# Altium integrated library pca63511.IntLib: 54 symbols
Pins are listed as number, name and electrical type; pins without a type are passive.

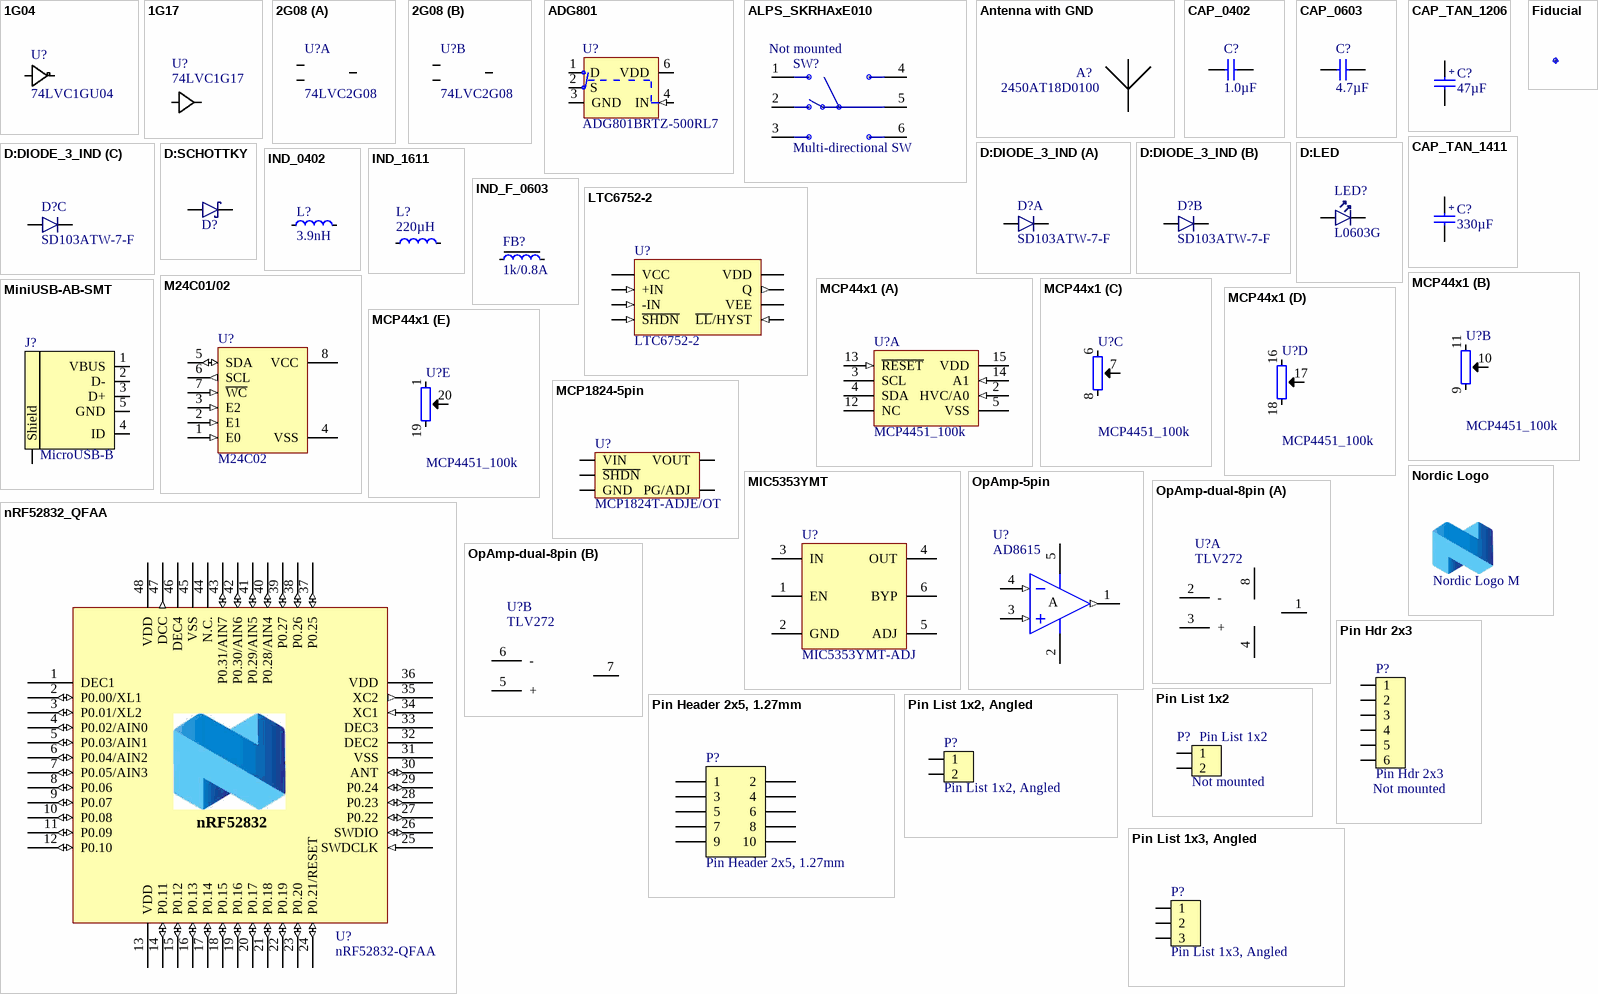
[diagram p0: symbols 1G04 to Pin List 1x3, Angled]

## 1G04
designator U?, comment 74LVC1GU04
Unbuffered Inverter; Manufacturer: NXP Semiconductors; 2nd source part number: 163-1691; Artikkelnr Noca: 15049405; Artikkelnr Simpro: N.A.
footprint SOT-353
pins: 1 N.C. hidden, 2 A, 3 GND hidden to GND, 4 Y, 5 VDD hidden to VDD

## 1G17
designator U?, comment 74LVC1G17
Single schmitt-trigger buffer with standard push-pull output; Part Number: 74LVC1G17SE; Manufacturer: Diodes; 2nd source part number: 189-3834; Artikkelnr Noca: 15049066; Artikkelnr Simpro: N.A.
footprint SOT-353
pins: 1 N.C. hidden, 2 A, 3 GND hidden to GND, 4 Y, 5 VDD hidden to VDD

## 2G08
designator U?, comment 74LVC2G08
IC DUAL 2IN POS-AND GATE SOT-1089; Part Number: 74LVC2G08GF; Manufacturer: NXP; Note: DUAL 2-INPUT POSITIVE-AND GATE; Artikkelnr Noca: 15049067; Artikkelnr Simpro: N.A.
footprint PSON35P100X50-8N
part A pins: 1 1A, 2 1B, 4 GND (power) hidden to GND "Ground", 7 1Y, 8 VDD (power) hidden to VDD
part B pins: 3 2Y, 5 2A, 6 2B

## ADG801
designator U?, comment ADG801BRTZ-500RL7
SWITCH SPST SOT23-6; Manufacturer: Analog Devices; 2nd source part number: 237-6778; Note: -40°C ~ 125°C; Artikkelnr Noca: 15079991; Artikkelnr Simpro: N.A.
footprint SOT95P280X145-6N
pins: 1 D, 2 S, 3 GND (power), 4 IN (in), 6 VDD (power)

## ALPS_SKRHAxE010
designator SW?, comment Multi-directional SW  Assembly: Not mounted
ALPS - SKRHAAE010, Multi-directional Switches 4-directn cntr push w/o boss 200K cycles, SMD, 7.5x7.5x5mm; Part Number: ALPS_SKRHAAE010; Artikkelnr Noca: 50019040; Artikkelnr Simpro: N.A.
footprint ALPS_SKRHAAE010
pins: 1 (power), 2 (power), 3 (power), 4 (power), 5 (power), 6 (power)

## Antenna with GND
designator A?, comment 2450AT18D0100
2.45 GHz chip antenna; Part Number: Johanson 2450AT18D0100_STD; Manufacturer: Johanson Technology; 2nd source part number: 609-2450AT18D0100E; Artikkelnr Noca: 53059035; Artikkelnr Simpro: N.A.
footprint 2450AT18D0100_STD
pins: 1, 2 GND (power) hidden to GND

## CAP_0402
designator C?, comment 1.0µF
Capacitor, X5R, ±5%; Part Number: C0402-1µ0; Note: 6.3V; Artikkelnr Noca: 20039235; Artikkelnr Simpro: N.A.
footprint CAPC1005X04L
pins: 1, 2

## CAP_0603
designator C?, comment 4.7µF
Capacitor, X5R, ±10%; Part Number: C0603-4µ7; Note: 6.3V; Artikkelnr Noca: 20069060; Artikkelnr Simpro: N.A.
footprint CAPC1608X06L
pins: 1, 2

## CAP_TAN_1206
designator C?, comment 47µF
Capacitor, Tantalum, ±10%; Part Number: C1206-47µ_Tantal; Note: 10V; Artikkelnr Noca: 20049200; Artikkelnr Simpro: N.A.
footprint CAPMP3216X18N
pins: 1, 2

## CAP_TAN_1411
designator C?, comment 330µF
Capacitor, Tantalum, ±20%, 3528; Part Number: C3528-330µF; Manufacturer: Kemet; Manufacturer Part Number: T490B337M006ATE800; Note: 6.3V; Artikkelnr Noca: 20049201; Artikkelnr Simpro: N.A.
footprint CAPMP3528X21N
pins: 1, 2

## D:DIODE_3_IND
designator D?, comment SD103ATW-7-F
Surface Mount Schottky Barrier Diode Array; Manufacturer: Diodes Incorporated; 2nd source part number: 177-3507; Artikkelnr Noca: 10029109; Artikkelnr Simpro: N.A.
footprint SOT-363
part A pins: 1 C1, 6 A1
part B pins: 2 C2, 5 A2
part C pins: 3 C3, 4 A3

## D:LED
designator LED?, comment L0603G
LED 0603, EL19-21SYGC; Manufacturer: Everlight; Manufacturer Part Number: 19-21SYGC/S530-E1/TR8; Note: 16 mcd @ 20 mA; Artikkelnr Noca: 13019044; Artikkelnr Simpro: N.A.
footprint LED_0603_G
pins: 1 C, 2 A

## D:SCHOTTKY
designator D?, comment 1PS79SB30.115  (value not drawn)
Diode Schottky Vf=0.38, Vr=40V, If=200mA, Ir=500nA; Manufacturer: NXP; Artikkelnr Noca: 10029120; Artikkelnr Simpro: N.A.
footprint SOD-523
pins: 1 A, 3 C

## Fiducial
designator Fid?, comment Fiducial mark  (value not drawn)
Part Number: Fid-Mark; Artikkelnr Noca: N.A.
footprint Fiducial

## IND_0402
designator L?, comment 3.9nH
Inductor, 170mA, ±0.1nH; Part Number: L0402-3n9; Manufacturer: Murata; Manufacturer Part Number: LQP15MN3N9B02D; Note: High frequency chip inductor ±5%; Artikkelnr Noca: 33029151; Artikkelnr Simpro: N.A.
footprint INDC1005X04L
pins: 1, 2

## IND_1611
designator L?, comment 220µH
FIXED IND 470UH 240MA 2.6 OHM; Part Number: L4848-220µH; Manufacturer: Bourns; Manufacturer Part Number: SRR4028-221Y; Note: -40°C ~ 125°C; Artikkelnr Noca: 33020083; Artikkelnr Simpro: N.A.
footprint WE-TPC_4848
pins: 1, 2

## IND_F_0603
designator FB?, comment 1k/0.8A
Ferrite Bead, 1 kOhm @ 100MHz, 800mA, 300 mOhm Max; Part Number: FB0603-1k@100MHz-800mA; Manufacturer: TDK; Manufacturer Part Number: MPZ1608S102ATA00; Note: Chip EMIFIL Inductor Type Chip Ferrite Bead; Artikkelnr Noca: 37029017; Artikkelnr Simpro: N.A.
footprint INDC1608X06L
pins: 1, 2

## LTC6752-2
designator U?
IC 2.9ns COMPARATOR, Rail-to-Rail input CMOS output, MSOP-8; Manufacturer: Linear Technology; Artikkelnr Noca: 17029058; Artikkelnr Simpro: N.A.
footprint MSOP65P490X110-8N
pins: 1 VCC (power), 2 +IN (in), 3 -IN (in), 4 ~{SHDN} (in), 5 ~{LL}/HYST (in), 6 VEE (power), 7 Q (out), 8 VDD (power)

## M24C01/02
designator U?, comment M24C02
2-Kbit serial I²C bus EEPROM; Part Number: M24C02-FDW6TP; Manufacturer: STMicroelectronics; Artikkelnr Noca: 15020011; Artikkelnr Simpro: N.A.
footprint TSOP65P640X120-8N
pins: 1 E0 (in), 2 E1 (in), 3 E2 (in), 4 VSS (power), 5 SDA (io), 6 SCL (out), 7 ~{WC} (in), 8 VCC (power)

## MCP44x1
designator U?, comment MCP4451_100k
Quad Digital Potentiometer, 100k, 257 taps, I2C interface, Volatile Memory, 1.8-5.5V; Manufacturer: Microchip Technology; Manufacturer Part Number: MCP4451-104E/ML; 2nd source part number: 579-MCP4451-104E/ML; Artikkelnr Noca: 15070064; Artikkelnr Simpro: N.A.
footprint QFN50P400X400X80_HS-21N
part A pins: 2 HVC/A0 (in), 3 SCL, 4 SDA, 5 VSS (power), 12 NC, 13 ~{RESET} (in), 14 A1 (in), 15 VDD (power) "VDD 1.65V - 5.5V", 21 VSS (power) hidden to GND
part B pins: 9 P0A, 10 P0W (power), 11 P0B
part C pins: 6 P1B, 7 P1W (power), 8 P1A
part D pins: 16 P2B, 17 P2W (power), 18 P2A
part E pins: 1 P3B, 19 P3A, 20 P3W (power)

## MCP1824-5pin
designator U?, comment MCP1824T-ADJE/OT
300 mA, Low Voltage, Low Quiescent Current LDO Regulator; Manufacturer: Microchip; Artikkelnr Noca: 17030009; Artikkelnr Simpro: N.A.
footprint SOT-23-5
pins: 1 VIN, 2 GND, 3 ~{SHDN}, 4 PG/ADJ, 5 VOUT

## MIC5353YMT
designator U?, comment MIC5353YMT-ADJ
500mA LDO adjustable; Manufacturer: Microchip Technology; Artikkelnr Noca: 17030072; Artikkelnr Simpro: N.A.
footprint QFN50P160X160X60_6N
pins: 1 EN, 2 GND (power), 3 IN (power), 4 OUT (power), 5 ADJ (power), 6 BYP (power), 7 GND hidden to GND

## MiniUSB-AB-SMT
designator J?, comment MicroUSB-B
MicroUSB-B-SMT; Part Number: USB-Micro-B-RA-SMD-PiP; Manufacturer: Allen Creations Corp.; Manufacturer Part Number: AJU55-BS2111-L; 2nd source part number: 609-4616-1-ND; Artikkelnr Noca: 55029020; Artikkelnr Simpro: N.A.
footprint USB-Micro-B-RA-SMD-PiP
pins: 1 VBUS (power), 2 D-, 3 D+, 4 ID, 5 GND (power), 6 Shield (power)

## Nordic Logo
designator LOGO?, comment Nordic Logo M  (no BOM)
Nordic Logo, medium size; Artikkelnr Noca: N.A.
footprint NORDIC_LOGO_M

## nRF52832_QFAA
designator U?, comment nRF52832-QFAA
Multi-protocol Bluetooth Low Energy and 2.4GHz proprietary system-on-chip; Manufacturer: Nordic Semiconductor; Artikkelnr Noca: 15079306; Artikkelnr Simpro: N.A.
footprint QFN40P600X600X90-48N
pins: 1 DEC1 (power), 2 P0.00/XL1 (io), 3 P0.01/XL2 (io), 4 P0.02/AIN0 (io), 5 P0.03/AIN1 (io), 6 P0.04/AIN2 (io), 7 P0.05/AIN3 (io), 8 P0.06 (io), 9 P0.07 (io), 10 P0.08 (io), 11 P0.09 (io), 12 P0.10 (io), 13 VDD (power), 14 P0.11 (io), 15 P0.12 (io), 16 P0.13 (io), 17 P0.14 (io), 18 P0.15 (io), 19 P0.16 (io), 20 P0.17 (io), 21 P0.18 (io), 22 P0.19 (io), 23 P0.20 (io), 24 P0.21/RESET (io), 25 SWDCLK (in), 26 SWDIO (io), 27 P0.22 (io), 28 P0.23 (io), 29 P0.24 (io), 30 ANT (io), 31 VSS (power), 32 DEC2 (power), 33 DEC3 (power), 34 XC1 (in), 35 XC2 (out), 36 VDD (power), 37 P0.25 (io), 38 P0.26 (io), 39 P0.27 (io), 40 P0.28/AIN4 (io), 41 P0.29/AIN5 (io), 42 P0.30/AIN6 (io), 43 P0.31/AIN7 (io), 44 N.C. (power), 45 VSS (power), 46 DEC4 (power), 47 DCC (out), 48 VDD (power), 49 GND (power) hidden to GND

## OpAmp-5pin
designator U?, comment AD8615
IC OPAMP GP 24MHZ RRO TSOT23-5; Part Number: AD8615AUJZ-REEL7; Manufacturer: Analog Devices; Artikkelnr Noca: 17010015; Artikkelnr Simpro: N.A.
footprint SOT95P280X145-5N
pins: 1 OUT (out), 2 VSS (power), 3 IN+ (in), 4 IN- (in), 5 VDD (power)

## OpAmp-dual-8pin
designator U?, comment TLV272
Dual rail to rail CMOS Amplifier; Part Number: TLV272CM8-13; Manufacturer: Diodes Incorporated; Artikkelnr Noca: 17010014; Artikkelnr Simpro: N.A.
footprint MSOP65P490X110-8N
part A pins: 1 OUT, 2 -, 3 +, 4 -, 8 +
part B pins: 5 +, 6 -, 7 OUT

## Pin Hdr 2x3
designator P?  Assembly: Not mounted
Pin Header 2x3, 2.54mm (100mil) SMD; Part Number: Pin Header 2x3 SMD; Manufacturer: W-CON; Manufacturer Part Number: 1125-1203S0M116R1; 2nd source part number: TSM-103-01-L-DV; Artikkelnr Noca: 55010007; Artikkelnr Simpro: N.A.
footprint Molex 15-91-2060
pins: 1, 2, 3, 4, 5, 6

## Pin Header 2x5, 1.27mm
designator P?
Pin Header 2x5, 1.27mm (50mil), SMD, Keying Shroud; Part Number: Pin Header 2x5 SMD, 1.27mm, KS; Manufacturer: W-CON; Manufacturer Part Number: 3132-10MS0BK00R1; 2nd source part number: FTSH-105-01-F-DV-K; Artikkelnr Noca: 55010009; Artikkelnr Simpro: N.A.
footprint HDR_2x5-SMD-1.27mm-K
pins: 1, 2, 3, 4, 5, 6, 7, 8, 9, 10

## Pin List 1x2
designator P?  Assembly: Not mounted
Pin List 1x2, 2.54mm (100mil); Artikkelnr Noca: 56019040; Artikkelnr Simpro: N.A.
footprint LIST_1x2
pins: 1, 2

## Pin List 1x2, Angled
designator P?
Pin List 1x2, 2.54mm (100mil), Right Angled, SMD; Part Number: Pin List Ang 1x2 SMD, 2.54mm; Manufacturer: W-CON; Manufacturer Part Number: 1125B-1102S0Z135R2; 2nd source part number: TSM-102-01-L-SH-A; Artikkelnr Noca: 55010023; Artikkelnr Simpro: N.A.
footprint LIST_ANG_1x2-SMD-2.54MM
pins: 1, 2

## Pin List 1x3, Angled
designator P?
Pin List 1x3, 2.54mm (100mil), Right Angled, SMD; Part Number: Pin List Ang 1x3 SMD, 2.54mm; Manufacturer: W-CON; Manufacturer Part Number: 1125B-1103S0Z135R2; 2nd source part number: TSM-103-01-L-SH-A; Artikkelnr Noca: 55019288; Artikkelnr Simpro: N.A.
footprint LIST_ANG_1x3-SMD-2.54MM
pins: 1, 2, 3 (power)

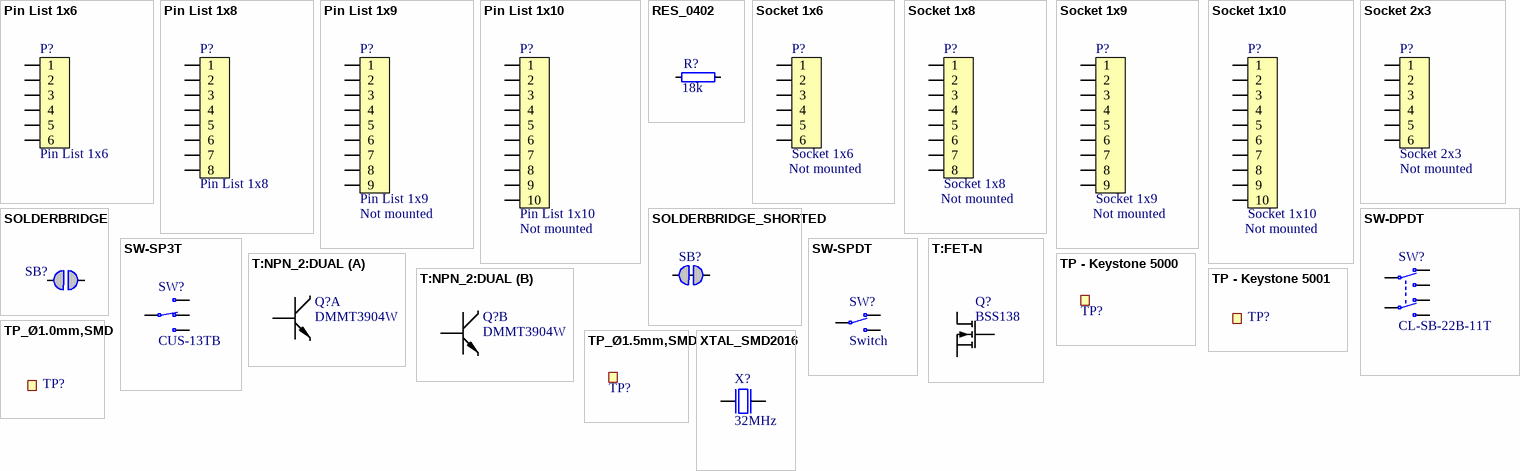
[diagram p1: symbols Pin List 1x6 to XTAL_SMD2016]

## Pin List 1x6
designator P?
Pin List 1x6, 2.54mm (100mil), SMD; Part Number: Pin List 1x6 SMD; Manufacturer: W-CON; Manufacturer Part Number: 1125-1106S0M116R2; 2nd source part number: TSM-106-01-L-SV-P-TR; Artikkelnr Noca: 55019252; Artikkelnr Simpro: N.A.
footprint LIST_1x6_SMD
pins: 1, 2, 3, 4, 5, 6

## Pin List 1x8
designator P?
Pin List 1x8, 2.54mm (100mil), SMD; Part Number: Pin List 1x8 SMD; Manufacturer: W-CON; Manufacturer Part Number: 1125-1108S0M116R2; 2nd source part number: TSM-108-01-L-SV-P-TR; Artikkelnr Noca: 55010006; Artikkelnr Simpro: N.A.
footprint LIST_1x8_SMD
pins: 1, 2, 3, 4, 5, 6, 7, 8

## Pin List 1x9
designator P?  Assembly: Not mounted
Pin List 1x9, 2.54mm (100mil), SMD; Part Number: Pin List 1x9 SMD; Manufacturer: W-CON; Manufacturer Part Number: 1125-1109S0M116R2; 2nd source part number: TSM-109-01-L-SV-P-TR; Artikkelnr Noca: 55010024; Artikkelnr Simpro: N.A.
footprint LIST_1x9_SMD
pins: 1, 2, 3 (power), 4 (power), 5 (power), 6 (power), 7 (power), 8 (power), 9 (power)

## Pin List 1x10
designator P?  Assembly: Not mounted
Pin List 1x10, 2.54mm (100mil), SMD; Part Number: Pin List 1x10 SMD; Manufacturer: W-CON; Manufacturer Part Number: 1125-1110S0M116R2; 2nd source part number: TSM-110-01-L-SV-P-TR; Artikkelnr Noca: 55019254; Artikkelnr Simpro: N.A.
footprint LIST_1x10_SMD
pins: 1, 2, 3, 4, 5, 6, 7, 8, 9, 10

## RES_0402
designator R?, comment 18k
Resistor, ±1%, 0.063W; Part Number: R0402-18k; Note: Chip Res 1%; Artikkelnr Noca: 27049103; Artikkelnr Simpro: N.A.; Value Ohm: 18000
footprint RESC1005X04L
pins: 1, 2

## Socket 1x6
designator P?  Assembly: Not mounted
Socket 1x6, 2.54mm (100mil), SMD; Part Number: Socket 1x6 SMD; Manufacturer: W-CON; Manufacturer Part Number: 2171-106MS0CUNR1; 2nd source part number: SSM-106-F-SV-P-TR; Artikkelnr Noca: 55030001; Artikkelnr Simpro: N.A.
footprint SOCKET_1x6_SMD
pins: 1, 2, 3, 4, 5, 6

## Socket 1x8
designator P?  Assembly: Not mounted
Socket 1x8, 2.54mm (100mil), SMD; Part Number: Socket 1x8 SMD; Manufacturer: W-CON; Manufacturer Part Number: 2171-108MS0CUNR1; 2nd source part number: SSM-108-F-SV-P-TR; Artikkelnr Noca: 55030002; Artikkelnr Simpro: N.A.
footprint SOCKET_1x8_SMD
pins: 1, 2, 3, 4, 5, 6, 7, 8

## Socket 1x9
designator P?  Assembly: Not mounted
Socket 1x9, 2.54mm (100mil), SMD; Part Number: Socket 1x9 SMD; Manufacturer: W-CON; Manufacturer Part Number: 2171-109MS0CUNR1; 2nd source part number: SSM-109-L-SV; Artikkelnr Noca: 55030003; Artikkelnr Simpro: N.A.
footprint SOCKET_1x9_SMD
pins: 1, 2, 3 (power), 4 (power), 5 (power), 6 (power), 7 (power), 8 (power), 9 (power)

## Socket 1x10
designator P?  Assembly: Not mounted
Socket 1x10, 2.54mm (100mil), SMD; Part Number: Socket 1x10 SMD; Manufacturer: W-CON; Manufacturer Part Number: 2171-110MS0CUNR1; 2nd source part number: SSM-110-F-SV-P-TR; Artikkelnr Noca: 55030004; Artikkelnr Simpro: N.A.
footprint SOCKET_1x10_SMD
pins: 1, 2, 3, 4, 5, 6, 7, 8, 9, 10

## Socket 2x3
designator P?  Assembly: Not mounted
Socket 2x3, 2.54mm (100mil), SMD; Part Number: Socket 2x3 SMD Bottom; Manufacturer: W-CON; Manufacturer Part Number: 2171-203MS0CUNR1; 2nd source part number: SSM-103-F-DV-P-TR; Artikkelnr Noca: 55019255; Artikkelnr Simpro: N.A.
footprint SOCKET_2x3_SMD-2.54mm-bottom
pins: 1, 2, 3, 4, 5, 6

## SOLDERBRIDGE
designator SB?, comment Solderbridge  (value not drawn)  (no BOM)
Artikkelnr Noca: N.A.
footprint Solderbridge
pins: 1 0, 2 1

## SOLDERBRIDGE_SHORTED
designator SB?, comment Solderbridge  (value not drawn)  (net tie, no BOM)
Shorted Solderbridge; Part Number: Solderbridge Shorted; Artikkelnr Noca: N.A.
footprint Solderbridge_Shorted
pins: 1 0, 2 1

## SW-DPDT
designator SW?, comment CL-SB-22B-11T
Slide Switch DPDT 200mA 12V; Manufacturer: Copal Electronics Inc; Artikkelnr Noca: 50019109; Artikkelnr Simpro: N.A.
footprint CL-SB-22B-1x
pins: 1 N.O-1, 2 COM-1, 3 N.C-1, 4 N.O-2, 5 COM-2, 6 N.C-2

## SW-SP3T
designator SW?, comment CUS-13TB
Low-profile slide switch, SP3T, ON-ON-ON; Manufacturer: Copal Electronics Inc; Artikkelnr Noca: 50029016; Artikkelnr Simpro: N.A.
footprint CUS-13B
pins: 1 N.O, 2 N.C, 3 COM, 4 N.O

## SW-SPDT
designator SW?, comment Switch
SMD slide Switch (ON-ON); Part Number: CJS-1200TA; Manufacturer: Copal Electronics Inc; Artikkelnr Noca: 50019068; Artikkelnr Simpro: N.A.
footprint CJS-120xA
pins: 1 N.C, 2 COM, 3 N.O

## T:FET-N
designator Q?, comment BSS138
60 V, 320 mA N-channel Trench MOSFET; Part Number: BSS138PW; Manufacturer: NXP; Manufacturer Part Number: BSS138PW,115; 2nd source part number: 568-10309-1-ND; Artikkelnr Noca: 35019197; Artikkelnr Simpro: N.A.
footprint SOT65P210X110-3N
pins: 1 G, 2 S, 3 D

## T:NPN_2:DUAL
designator Q?, comment DMMT3904W
40V Matched pair NPN Small signal transistor; Part Number: DMMT3904W-7-F; Manufacturer: Diodes Incorporated; 2nd source part number: 206-1407; Artikkelnr Noca: 35010017; Artikkelnr Simpro: N.A.
footprint SOT-363
part A pins: 2 B1, 3 C1, 4 E1
part B pins: 1 B2, 5 E2, 6 C2

## TP - Keystone 5000
designator TP?, comment TP  (value not drawn)  (no BOM)
Miniature THM Test Point -Red P/N 5000; Part Number: TP - Keystone 5000; Manufacturer: Keystone; Manufacturer Part Number: 5000; 2nd source part number: 5000K-ND; Note: Keystone 5000, RED; Artikkelnr Noca: N.A.; Assembly: Not Mounted
footprint TEST_POINT_5000
pins: 1

## TP - Keystone 5001
designator TP?, comment TP  (value not drawn)  (no BOM)
Miniature THM Test Point -Black P/N 5001; Part Number: TP - Keystone 5001; Manufacturer: Keystone; Manufacturer Part Number: 5001; 2nd source part number: 5001K-ND; Note: Keystone 5001, BLACK; Artikkelnr Noca: N.A.; Assembly: Not mounted
footprint TEST_POINT_5001
pins: 1

## TP_Ø1.0mm,SMD
designator TP?, comment Ø1.0mm,SMD  (value not drawn)  (no BOM)
1.0mm circular SMD testpad; Part Number: TP_SMD_Ø1.0MM; Manufacturer: Nordic Semiconductor; Artikkelnr Noca: N.A.
footprint TP_SMD_Ø1.0mm
footprint TP_SMD_Ø1.5MM
pins: 1

## TP_Ø1.5mm,SMD
designator TP?, comment Ø1.5mm,SMD  (value not drawn)  (no BOM)
1.5mm circular SMD testpad; Part Number: TP_SMD_Ø1.5MM; Manufacturer: Nordic Semiconductor; Artikkelnr Noca: N.A.
footprint TP_SMD_Ø1.5mm
pins: 1

## XTAL_SMD2016
designator X?, comment 32MHz
XTAL SMD 2016, 32MHz, Cl=8pF, Tot: ±40ppm; Part Number: XTAL_SMD2016_32MHz_8pF_Kyocera; Manufacturer: Kyocera; Manufacturer Part Number: CX2016DB32000D0WZRC1; Note: XTAL SMD 32.000MHz; Artikkelnr Noca: 22010022; Artikkelnr Simpro: N.A.
footprint BT-XTAL_2016
pins: 1 inp, 2 GND hidden to GND, 3 out, 4 GND hidden to GND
